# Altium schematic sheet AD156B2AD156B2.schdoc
size 127 x 101 mm
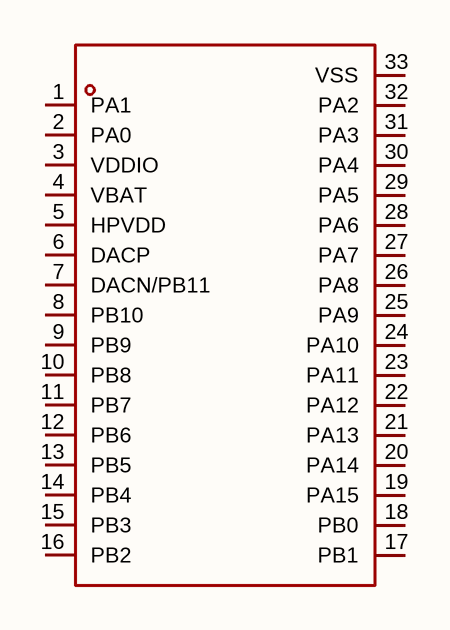
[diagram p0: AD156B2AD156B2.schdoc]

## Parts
U?  ad156b2  [QFN-32_L4.0-W4.0-P0.40-TL-EP2.7]  (value not drawn)

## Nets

Not connected (* = marked no-connect by the designer): U? 1(PA1) 2(PA0) 3(VDDIO) 4(VBAT) 5(HPVDD) 6(DACP) 7(DACN/PB11) 8(PB10) 9(PB9) 10(PB8) 11(PB7) 12(PB6) 13(PB5) 14(PB4) 15(PB3) 16(PB2) 17(PB1) 18(PB0) 19(PA15) 20(PA14) 21(PA13) 22(PA12) 23(PA11) 24(PA10) 25(PA9) 26(PA8) 27(PA7) 28(PA6) 29(PA5) 30(PA4) 31(PA3) 32(PA2) 33(VSS)

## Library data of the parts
U? = ad156b2: CPU内核:-;CPU最大主频:120MHz;CPU位数:32bit;; Manufacturer: JL(杰理); AddInBom: yes; ModelId: 1e9eca8b25044b9fa4f766d7d1391f8f; ModelTransform: 158.267,158.267,0,0,0,0,0,0,0; CPU Maximum Speed: 120MHz; Core Size: 32bit; Number of I/O: 28; ADC (Bit): 10bit; Voltage - Supply: 2V~5.5V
